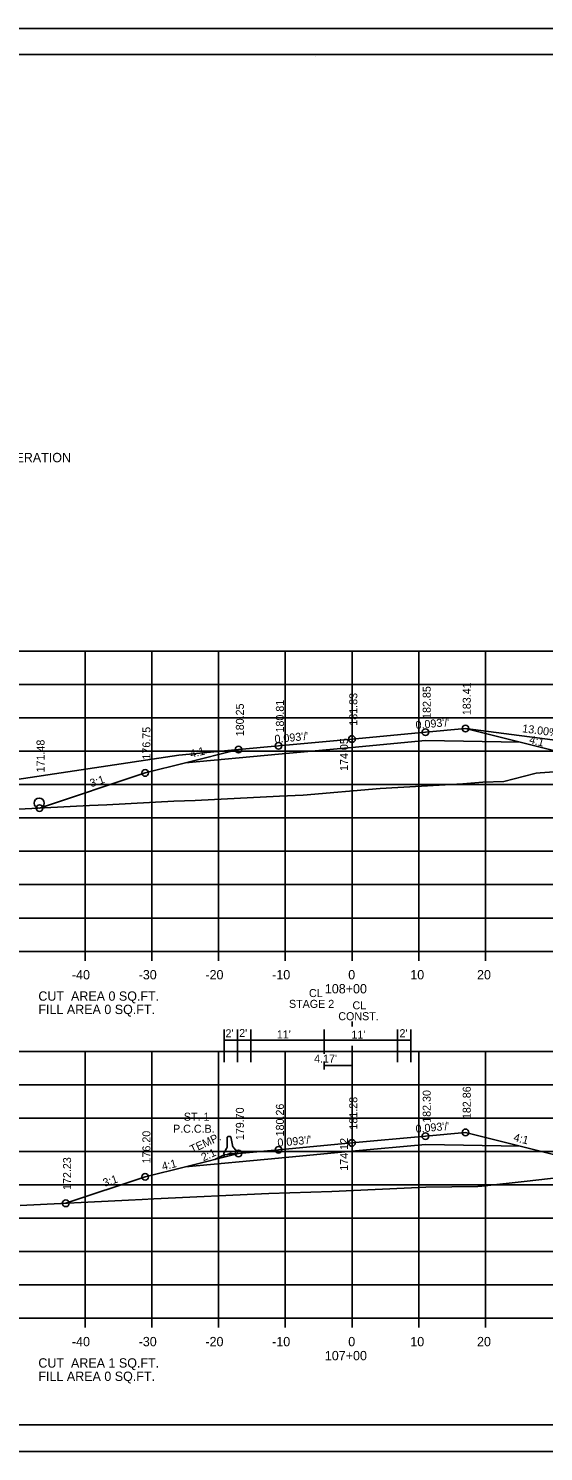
# Model space of a CAD drawing. Extents: x 915787 to 919910, y 133456 to 136717.
# Drawn here: x 916365.5 to 916442.7, y 133882.7 to 134096 of the extents above; entities that cross this region are included whole.
import ezdxf

# ---------------------------------------------------------------- set-up
doc = ezdxf.new("R2010")
doc.units = 0
for name, color, linetype in [('R_Axis', 7, 'Continuous'), ('R_Axis Annot', 7, 'Continuous'), ('R_Border', 7, 'Continuous'), ('R_Border Notes', 7, 'Continuous'), ('R_Drive', 7, 'Continuous'), ('R_Exist Surface', 7, 'Continuous'), ('R_Fin Surface', 7, 'Continuous'), ('R_Grid', 7, 'Continuous'), ('R_MOT', 7, 'Continuous'), ('R_No Plot', 7, 'Continuous'), ('R_Water', 7, 'Continuous'), ('R_Xsect Elev', 7, 'Continuous'), ('R_Xsect Slope', 7, 'Continuous')]:
    doc.layers.add(name, color=color, linetype=linetype)

msp = doc.modelspace()

# ---------------------------------------------------------------- linework, layer by layer
at = {"layer": 'R_Axis'}
for p, q in [((916273.98, 133957.69), (916553.98, 133957.69)), ((916373.98, 133956.29), (916373.98, 133957.69)), ((916383.98, 133956.29), (916383.98, 133957.69)), ((916393.98, 133956.29), (916393.98, 133957.69)), ((916403.98, 133956.29), (916403.98, 133957.69)), ((916413.98, 133956.29), (916413.98, 133957.69)), ((916423.98, 133956.29), (916423.98, 133957.69)), ((916433.98, 133956.29), (916433.98, 133957.69)), ((916273.98, 133902.69), (916553.98, 133902.69)), ((916373.98, 133901.29), (916373.98, 133902.69)), ((916383.98, 133901.29), (916383.98, 133902.69)), ((916393.98, 133901.29), (916393.98, 133902.69)), ((916403.98, 133901.29), (916403.98, 133902.69)), ((916413.98, 133901.29), (916413.98, 133902.69)), ((916423.98, 133901.29), (916423.98, 133902.69)), ((916433.98, 133901.29), (916433.98, 133902.69))]:
    msp.add_line(p, q, dxfattribs=at)
at = {"layer": 'R_Border'}
for p, q in [((916255.98, 134092.15), (916572.16, 134092.15)), ((916408.5, 134091.89), (916408.5, 134091.89)), ((916408.5, 134091.89), (916408.5, 134091.89)), ((916572.16, 133886.69), (916255.98, 133886.69))]:
    msp.add_line(p, q, dxfattribs=at)
at = {"layer": 'R_Border Notes'}
for p, q in [((916413.98, 133946.42), (916413.98, 133947.16)), ((916413.98, 133939.62), (916413.98, 133943.55)), ((916409.81, 133939.97), (916409.81, 133941.2)), ((916409.81, 133940.56), (916413.98, 133940.56))]:
    msp.add_line(p, q, dxfattribs=at)
at = {"layer": 'R_Drive'}
for q in [(916296.71, 133973.41), (916396.97, 133987.94)]:
    msp.add_line((916388.01, 133987.11), q, dxfattribs=at)
at = {"layer": 'R_Exist Surface'}
for points in [[(916364.03, 133979.01), (916374.65, 133979.56), (916377.22, 133979.67), (916387.27, 133980.19), (916390.47, 133980.33), (916403.11, 133980.97), (916406.65, 133981.13), (916418.2, 133982.1), (916430.57, 133982.81), (916433.6, 133983.04), (916436.74, 133983.16), (916441.35, 133984.36), (916441.58, 133984.42), (916442.16, 133984.46), (916454.05, 133985.31)], [(916364.27, 133919.58), (916380.49, 133920.4), (916382.53, 133920.48), (916384.27, 133920.59), (916401.53, 133921.38), (916410.95, 133921.67), (916425.05, 133922.32), (916432.85, 133922.42), (916433.42, 133922.51), (916440.23, 133923.25), (916451.11, 133924.51)]]:
    msp.add_lwpolyline(points, dxfattribs=at)
at = {"layer": 'R_Fin Surface'}
for points in [[(916367.16, 133979.17), (916382.97, 133984.44), (916389.01, 133985.95), (916396.97, 133987.94), (916402.97, 133988.5), (916413.97, 133989.52), (916424.97, 133990.54), (916430.97, 133991.1), (916439.17, 133989.05), (916444.97, 133987.6), (916452.24, 133985.18), (916509.8, 133984.03)], [(916389.01, 133985.95), (916402.97, 133987.25), (916413.97, 133988.27), (916424.97, 133989.29), (916439.17, 133989.05)], [(916371.08, 133919.92), (916382.97, 133923.89), (916389.01, 133925.4), (916396.97, 133927.39), (916402.97, 133927.95), (916413.97, 133928.97), (916424.97, 133929.99), (916430.97, 133930.55), (916439.17, 133928.5), (916444.97, 133927.05), (916452.02, 133924.7), (916507.27, 133923.6)], [(916389.01, 133925.4), (916402.97, 133926.7), (916413.97, 133927.72), (916424.97, 133928.74), (916439.17, 133928.5)]]:
    msp.add_lwpolyline(points, dxfattribs=at)
at = {"layer": 'R_Grid'}
for p, q in [((916273.98, 134002.69), (916553.98, 134002.69)), ((916373.98, 133957.69), (916373.98, 134002.69)), ((916383.98, 133957.69), (916383.98, 134002.69)), ((916393.98, 133957.69), (916393.98, 134002.69)), ((916403.98, 133957.69), (916403.98, 134002.69)), ((916413.98, 133957.69), (916413.98, 134002.69)), ((916423.98, 133957.69), (916423.98, 134002.69)), ((916433.98, 133957.69), (916433.98, 134002.69)), ((916273.98, 133997.69), (916553.98, 133997.69)), ((916273.98, 133992.69), (916553.98, 133992.69)), ((916273.98, 133987.69), (916553.98, 133987.69)), ((916273.98, 133982.69), (916553.98, 133982.69)), ((916273.98, 133977.69), (916553.98, 133977.69)), ((916273.98, 133972.69), (916553.98, 133972.69)), ((916273.98, 133967.69), (916553.98, 133967.69)), ((916273.98, 133962.69), (916553.98, 133962.69)), ((916273.98, 133957.69), (916553.98, 133957.69)), ((916273.98, 133942.69), (916553.98, 133942.69)), ((916373.98, 133902.69), (916373.98, 133942.69)), ((916383.98, 133902.69), (916383.98, 133942.69)), ((916393.98, 133902.69), (916393.98, 133942.69)), ((916403.98, 133902.69), (916403.98, 133942.69)), ((916413.98, 133902.69), (916413.98, 133942.69)), ((916423.98, 133902.69), (916423.98, 133942.69)), ((916433.98, 133902.69), (916433.98, 133942.69)), ((916273.98, 133937.69), (916553.98, 133937.69)), ((916273.98, 133932.69), (916553.98, 133932.69)), ((916273.98, 133927.69), (916553.98, 133927.69)), ((916273.98, 133922.69), (916553.98, 133922.69)), ((916273.98, 133917.69), (916553.98, 133917.69)), ((916273.98, 133912.69), (916553.98, 133912.69)), ((916273.98, 133907.69), (916553.98, 133907.69)), ((916273.98, 133902.69), (916553.98, 133902.69))]:
    msp.add_line(p, q, dxfattribs=at)
at = {"layer": 'R_MOT'}
for p, q in [((916395.29, 133929.85), (916395.28, 133928.54)), ((916395.29, 133929.85), (916395.36, 133929.92)), ((916395.36, 133929.92), (916395.73, 133929.96)), ((916395.73, 133929.96), (916395.8, 133929.9)), ((916395.8, 133929.9), (916396.07, 133928.62)), ((916395.18, 133928.14), (916394.78, 133927.44)), ((916394.78, 133927.44), (916394.81, 133927.19)), ((916395.3, 133927.24), (916394.81, 133927.19)), ((916395.3, 133927.24), (916395.78, 133927.45)), ((916395.78, 133927.45), (916396.3, 133927.33)), ((916396.25, 133928.24), (916396.77, 133927.63)), ((916396.3, 133927.33), (916396.8, 133927.38)), ((916396.77, 133927.63), (916396.8, 133927.38))]:
    msp.add_line(p, q, dxfattribs=at)
for centre, start, end in [((916394.45, 133928.55), 330.5442, 359.5272), ((916396.88, 133928.78), 191.5452, 220.5282)]:
    msp.add_arc(centre, 0.833, start, end, dxfattribs=at)
at = {"layer": 'R_No Plot'}
for p, q in [((916243.57, 134096.05), (916576.91, 134096.05)), ((916243.57, 133882.71), (916576.91, 133882.71))]:
    msp.add_line(p, q, dxfattribs=at)
for points in [[(916243.57, 134096.05), (916576.91, 134096.05), (916576.91, 133882.71), (916243.57, 133882.71)], [(916489.9, 134092.15), (916489.9, 134082.27), (916525.63, 134082.27), (916525.63, 134079.35), (916548.83, 134079.35), (916548.83, 134056.14), (916572.16, 134056.14), (916572.16, 133886.69), (916255.98, 133886.69), (916255.98, 134092.15)]]:
    msp.add_lwpolyline(points, close=True, dxfattribs=at)
for centre in [(916424.97, 133990.54), (916424.97, 133990.54), (916430.97, 133991.1), (916430.97, 133991.1), (916402.97, 133988.5), (916402.97, 133988.5), (916413.97, 133989.52), (916413.97, 133989.52), (916396.97, 133987.94), (916396.97, 133987.94), (916382.97, 133984.44), (916382.97, 133984.44), (916367.16, 133979.17), (916367.16, 133979.17), (916413.97, 133928.97), (916413.97, 133928.97), (916424.97, 133929.99), (916424.97, 133929.99), (916430.97, 133930.55), (916430.97, 133930.55), (916396.97, 133927.39), (916396.97, 133927.39), (916402.97, 133927.95), (916402.97, 133927.95), (916382.97, 133923.89), (916382.97, 133923.89), (916371.08, 133919.92), (916371.08, 133919.92)]:
    msp.add_circle(centre, 0.5, dxfattribs=at)
at = {"layer": 'R_Water'}
msp.add_circle((916367.1, 133979.92), 0.75, dxfattribs=at)
at = {"layer": 'R_Xsect Slope'}
for p, q in [((916463.54, 133986.88), (916430.97, 133991.1)), ((916394.81, 133941.07), (916394.81, 133945.99)), ((916394.81, 133944.37), (916422.81, 133944.37)), ((916396.81, 133941.07), (916396.81, 133945.99)), ((916398.81, 133941.07), (916398.81, 133945.99)), ((916409.81, 133942.32), (916409.81, 133945.99)), ((916420.81, 133941.07), (916420.81, 133945.99)), ((916422.81, 133941.07), (916422.81, 133945.99)), ((916394.81, 133927.19), (916393.4, 133926.5)), ((916402.97, 133927.95), (916394.81, 133927.19))]:
    msp.add_line(p, q, dxfattribs=at)
msp.add_lwpolyline([(916394.84, 133926.86), (916394.81, 133927.19)], dxfattribs=at)

# ---------------------------------------------------------------- texts
at = {"layer": 'R_Axis Annot'}
for s, p in [('-40', (916372.01, 133953.49)), ('-30', (916382.01, 133953.49)), ('-20', (916392.01, 133953.49)), ('-10', (916402.01, 133953.49)), ('0', (916413.41, 133953.49)), ('10', (916422.71, 133953.49)), ('20', (916432.71, 133953.49)), ('108+00', (916409.91, 133951.39)), ('-40', (916372.01, 133898.49)), ('-30', (916382.01, 133898.49)), ('-20', (916392.01, 133898.49)), ('-10', (916402.01, 133898.49)), ('0', (916413.41, 133898.49)), ('10', (916422.71, 133898.49)), ('20', (916432.71, 133898.49)), ('107+00', (916409.91, 133896.39))]:
    msp.add_text(s, height=1.4, dxfattribs=at).set_placement(p)
at = {"layer": 'R_Border Notes'}
for s, height, p in [('OLITERATION', 1.4, (916359.39, 134031.02)), ('CUT  AREA 0 SQ.FT.', 1.4, (916366.98, 133950.29)), ('STAGE 2', 1.2, (916404.53, 133949.22)), ('CL', 1.2, (916407.53, 133950.84)), ('FILL AREA 0 SQ.FT.', 1.4, (916366.98, 133948.29)), ('CONST.', 1.2, (916411.92, 133947.37)), ('CL', 1.2, (916414.05, 133949)), ("4.17'", 1.2, (916408.3, 133941.01)), ('CUT  AREA 1 SQ.FT.', 1.4, (916366.98, 133895.29)), ('FILL AREA 0 SQ.FT.', 1.4, (916366.98, 133893.29))]:
    msp.add_text(s, height=height, dxfattribs=at).set_placement(p)
at = {"layer": 'R_Drive'}
msp.add_text('13.00% TEMP. DRIVE', height=1.2, rotation=352.6075, dxfattribs=at).set_placement((916439.44, 133990.55))
at = {"layer": 'R_MOT'}
msp.add_text('DWB 1-14-10', height=0.004, rotation=95.5362, dxfattribs=at).set_placement((916394.81, 133927.2))
at = {"layer": 'R_Xsect Elev'}
for s, p in [('182.85', (916425.77, 133992.54)), ('183.41', (916431.77, 133993.1)), ('180.81', (916403.77, 133990.5)), ('181.83', (916414.77, 133991.52)), ('180.25', (916397.77, 133989.94)), ('176.75', (916383.77, 133986.44)), ('171.48', (916367.9, 133984.52)), ('174.05', (916413.38, 133984.74)), ('181.28', (916414.77, 133930.97)), ('182.30', (916425.77, 133931.99)), ('182.86', (916431.77, 133932.55)), ('179.70', (916397.77, 133929.39)), ('180.26', (916403.77, 133929.95)), ('176.20', (916383.77, 133925.89)), ('174.12', (916413.38, 133924.81)), ('172.23', (916371.88, 133921.92))]:
    msp.add_text(s, height=1.2, rotation=90, dxfattribs=at).set_placement(p)
at = {"layer": 'R_Xsect Slope'}
for s, rotation, p in [("0.093'/'", 5.3132, (916423.56, 133991.01)), ("0.093'/'", 5.3132, (916402.42, 133988.92)), ('4:1', 345.9638, (916440.44, 133988.92)), ('4:1', 14.0362, (916389.85, 133986.68)), ('3:1', 18.4349, (916374.91, 133982.28)), ("0.093'/'", 5.3132, (916423.56, 133930.47)), ('TEMP.', 24.829, (916390.02, 133927.4)), ("0.093'/'", 5.3132, (916402.86, 133928.4)), ('4:1', 345.9638, (916438.1, 133929.29)), ('2:1', 24.829, (916391.7, 133926.19)), ('4:1', 14.0362, (916385.63, 133924.84)), ('3:1', 18.4349, (916376.87, 133922.38))]:
    msp.add_text(s, height=1.2, rotation=rotation, dxfattribs=at).set_placement(p)
for s, p in [("2'", (916395.02, 133944.81)), ("2'", (916397.07, 133944.85)), ("11'", (916402.71, 133944.64)), ("11'", (916413.89, 133944.61)), ("2'", (916421.09, 133944.82)), ('ST. 1', (916388.78, 133932.3)), ('P.C.C.B.', (916387.16, 133930.5))]:
    msp.add_text(s, height=1.2, dxfattribs=at).set_placement(p)

doc.saveas('drawing.dxf')
